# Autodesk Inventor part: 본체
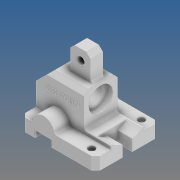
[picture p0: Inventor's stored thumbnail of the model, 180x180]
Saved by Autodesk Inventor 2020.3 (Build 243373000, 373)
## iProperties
Created: 2022-08
Part Number: 본체
Material: 알루미늄 6061
Document SubType Name: Modeling
Designer: EZDESIGN
Density: 2.7 g/cm^3
Appearance: 기본값
Mass: 501.268 g
Surface Area: 340.321 cm^2
Volume: 185.655 cm^3
Author: EZDESIGN
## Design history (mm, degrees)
sketch "스케치1"
  geometry: L1 (0, 15)-(90, 15); L2 (90, 15)-(90, 0); L3 (90, 0)-(0, 0); L4 (0, 0)-(0, 15); C1 r 13 at (27, 15); 3 further points
  constraints: 8 end point, 2 parallel, 1 centre point, 1 coincident, 1 horizontal, 1 perpendicular, 1 point on line
  dimensions: "d0" = 15 distance of L3.end L1.start; "d1" = 90 distance of L2.end L3.end; "d18" = 26 diameter of C1; "d19" = 27 distance from line of L4 C1.centre
extrude "돌출1" new body sketch "스케치1" distance "d4" = 18; taper "d5" = 0 deg
sketch "스케치2"
  geometry: L1 (0, 15)-(0, 0) reference; L2 (0, 15)-(0, 42); L3 (0, 42)-(-18, 60); L4 (-18, 60)-(-58, 60); L5 (-58, 60)-(-58, 19); L6 (-58, 19)-(-90, 19); L7 (-90, 19)-(-90, 15); L8 (-90, 0)-(-90, 15) reference; L9 (-90, 15)-(0, 15) reference; L10 (0, 0)-(-90, 0) reference; 1 further point
  constraints: 12 end point, 4 perpendicular, 1 collinear, 1 vertical
  dimensions: "d7" = 45 distance between parallel lines of L9 L4; "d8" = 45 deg angle of L3 L2; "d9" = 18 horizontal distance of L2.end L3.end; "d10" = 32 distance between parallel lines of L7 L5; "d11" = 19 distance between parallel lines of L10 L6
extrude "돌출2" join sketch "스케치2" distance "d12" = 40; taper "d13" = 0 deg
fillet "모깎기2" dims "d14" = 3
chamfer "모따기1" distance "d15" = 5; stored, may be unused: second distance "d16" = 2, angle "d17" = 45 deg
fillet "모깎기3" dims "d20" = 3
node "작업 평면1"
sketch "스케치5"
  geometry: L1 (58, 42)-(0, 42); L2 (0, 0)-(90, 0) reference; L3 (58, 55)-(58, 22) reference; L4 (0, 15)-(0, 42) reference; L5 (58, 42)-(58, 56.5); L6 (51, 56.5)-(51, 53); L7 (50, 52)-(0, 52); L8 (0, 52)-(0, 42); L9 (58, 56.5)-(51, 56.5); L10 (51, 53)-(50, 52); 3 further points
  constraints: 14 end point, 5 point on line, 2 horizontal, 2 perpendicular, 1 vertical
  dimensions: "d31" = 42 distance between parallel lines of L2 L1; "d32" = 29 diameter of L9 L1; "d33" = 20 diameter of L7 L1; "d34" = 7 distance of L5.end L6.start; "d35" = 1 distance of L6.end point (51, 52); "d36" = 1 distance of L7.start point (51, 52) (= d35)
revolve "회전1" sketch "스케치5" stored, may be unused: angle "d37" = 90 deg
sketch "스케치6"
  geometry: L1 (18, 19)-(58, 19) reference; L2 (32, 13.627)-(44, 13.627); L3 (44, 13.627)-(44, 0); L4 (44, 0)-(32, 0); L5 (32, 0)-(32, 13.627); L6 (0, 0)-(76, 0) reference; L7 (20.336, 19)-(55.664, 19); C1 r 14.5 at (38, 42) reference; A1 r 29 centre (38, 42) between (55.664, 19) and (20.336, 19); A2 r 29 centre (38, 42) between (20.336, 19) and (32, 13.627); A3 r 29 centre (38, 42) between (44, 13.627) and (55.664, 19); A4 r 29 centre (38, 42) between (32, 13.627) and (44, 13.627); 1 further point
  constraints: 10 end point, 9 point on circle, 4 centre point, 2 collinear, 2 parallel, 2 point on line, 1 coincident, 1 horizontal, 1 midpoint, 1 perpendicular, 1 vertical alignment
  dimensions: "d38" = 58 diameter of A1; "d39" = 12 distance of L3.end L4.end
extrude "돌출5" cut sketch "스케치6" distance "d40" = 18; taper "d41" = 0 deg
sketch "스케치7"
  geometry: L1 (58, 60)-(18, 60) reference; L2 (29, 60)-(29, 90); L3 (29, 90)-(53, 90); L4 (53, 90)-(53, 60); L5 (58, 55)-(58, 22) reference; 1 further point
  constraints: 6 end point, 2 point on line, 1 horizontal, 1 perpendicular, 1 vertical
  dimensions: "d42" = 24 distance of L2.end L3.end; "d43" = 5 distance between parallel lines of L5 L4; "d44" = 30 distance of L3.end L4.end
extrude "돌출6" join sketch "스케치7" stored distance "d45" = 15; taper "d46" = 0 deg
fillet "모깎기4" dims "d47" = 3
chamfer "모따기2" distance "d48" = 5; stored, may be unused: second distance "d49" = 2, angle "d50" = 45 deg
sketch "스케치8"
  geometry: L1 (53, 63)-(53, 85) reference; L2 (0, 0)-(90, 0) reference; 2 further points
  dimensions: "d58" = 12 distance from line of L1 point (41, 77); "d59" = 77 distance from line of L2 point (41, 77)
hole "구멍1" sketch "스케치8" at (41, 77) diameter "d51" = 8; stored, may be unused: countersink angle "d55" = 90 deg, drill point angle "d57" = 118 deg; dims "d52" = 6, "d53" = 4, "d54" = 2, "d56" = 8
chamfer "모따기3" distance "d60" = 1; stored, may be unused: second distance "d61" = 2, angle "d62" = 45 deg
sketch "스케치9"
  geometry: L1 (47.284, 0)-(47.284, -18) reference; L2 (47.284, 0)-(0, 0) reference; 2 further points
  dimensions: "d70" = 13 distance from line of L1 point (34.284, -8); "d71" = 8 distance from line of L2 point (34.284, -8)
hole "구멍2" sketch "스케치9" at (34.284, -8) diameter "d63" = 4.5; stored, may be unused: countersink angle "d67" = 90 deg, drill point angle "d69" = 118 deg; dims "d64" = 6, "d65" = 8, "d66" = 4.4, "d68" = 8
sketch "스케치10"
  geometry: L1 (58, 55)-(58, 22) reference; L2 (58, 60)-(18, 60) reference; 2 further points
  constraints: 1 other
  dimensions: "d75" = 26 distance from line of L1 point (32, 42); "d76" = 18 distance from line of point (32, 42) L2
feature "엠보싱1" sketch "스케치10" dims "d0" = 15, "d1" = 90, "d18" = 26, "d19" = 27, "d77" = 0.5, "d78" = 0
sketch "스케치4"
  geometry: L1 (17, 8)-(37, 8); L2 (37, 8)-(37, 0); L3 (37, 0)-(17, 0); L4 (17, 0)-(17, 8); L5 (0, 0)-(90, 0) reference; A1 r 13 centre (27, 15) between (39.769, 17.438) and (14.231, 17.438) reference; 1 further point
  constraints: 8 end point, 2 parallel, 1 collinear, 1 horizontal, 1 midpoint, 1 perpendicular, 1 vertical alignment
  dimensions: "d26" = 20 distance of L1.start L1.end; "d27" = 8 distance of L1.end L2.end
extrude "돌출7" cut sketch "스케치4" extent not by distance; stored distance "d79" = 0; taper "d80" = 0 deg
chamfer "모따기4" distance "d81" = 5; stored, may be unused: second distance "d82" = 2, angle "d83" = 45 deg
node "솔리드1"
mirror "미러1"
pattern_linear "직사각형 패턴1" dims "d74" = 60
feature "A9D066F2-1C7D-4E18-AEED-F7BC21143FA4" dims "d63" = 4.5, "d64" = 6, "d65" = 8, "d66" = 4.4, "d67" = 90 deg, "d68" = 8, "d69" = 118 deg
other parameters: "d30" = -38
